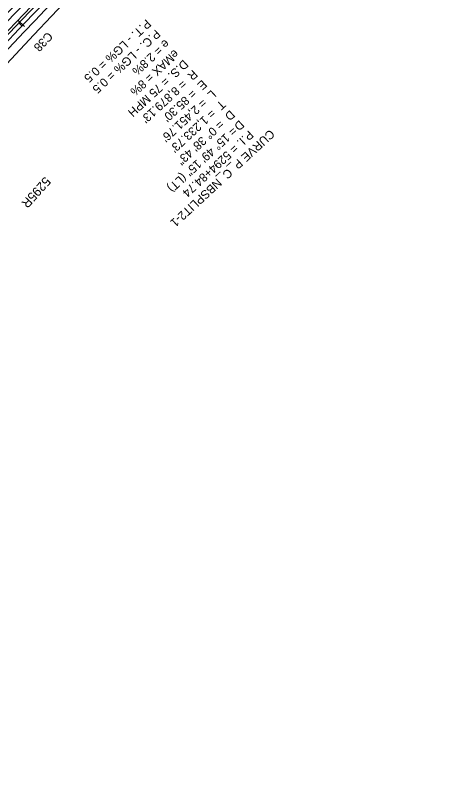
# Model space of a CAD drawing. Extents: x 2160877 to 2175861, y 601747 to 617724.
# Drawn here: x 2163357 to 2164133, y 604108 to 605468 of the extents above; entities that cross this region are included whole.
import ezdxf

# ---------------------------------------------------------------- set-up
doc = ezdxf.new("R2010")
doc.units = 0
for name, color, linetype in [('RD_HC_Cl', 7, 'Continuous'), ('RD_HC_CL_Rel', 7, 'Continuous'), ('RD_HC_Data_Rel', 7, 'Continuous'), ('RD_HC_Data_Tic', 7, 'Continuous'), ('RD_HC_Data_Tic_Rel', 7, 'Continuous'), ('RD_HC_TX_Rel_Sta50', 7, 'Continuous'), ('RD_PD_CstnLmt', 7, 'Continuous'), ('RD_PD_CstnLmt_TX', 7, 'Continuous'), ('RD_PD_Final_LnLine', 7, 'Continuous'), ('RD_PD_Final_TrvlWay', 7, 'Continuous')]:
    doc.layers.add(name, color=color, linetype=linetype)

msp = doc.modelspace()

# ---------------------------------------------------------------- linework, layer by layer
at = {"layer": 'RD_HC_Cl'}
for radius in [8641.9, 8545.9]:
    msp.add_arc((2169535, 599544.7), radius, 132.71947, 164.41949, dxfattribs=at)
at = {"layer": 'RD_HC_CL_Rel'}
for centre, radius, end in [((2169810, 599356.6), 8879.1, 145.62858), ((2169305.2, 599690.4), 8369.8, 147.62243)]:
    msp.add_arc(centre, radius, 129.80773, end, dxfattribs=at)
at = {"layer": 'RD_HC_Data_Tic'}
msp.add_line((2163362.5, 605455.2), (2163368.3, 605449.6), dxfattribs=at)
at = {"layer": 'RD_HC_Data_Tic_Rel'}
msp.add_line((2163361.2, 605460), (2163372.8, 605449), dxfattribs=at)
at = {"layer": 'RD_PD_CstnLmt'}
for p, q in [((2163457.1, 605506.3), (2163388.7, 605434)), ((2163388.7, 605434), (2163320.6, 605361.3))]:
    msp.add_line(p, q, dxfattribs=at)
at = {"layer": 'RD_PD_Final_LnLine'}
for centre, radius, end in [((2169810, 599356.6), 8891.1, 145.62858), ((2169810, 599356.6), 8867.1, 144.89859), ((2169305.2, 599690.4), 8381.8, 136.90521), ((2169305.2, 599690.4), 8357.8, 147.62243)]:
    msp.add_arc(centre, radius, 129.80773, end, dxfattribs=at)
at = {"layer": 'RD_PD_Final_TrvlWay'}
for centre, radius, start, end in [((2169810, 599356.6), 8901.1, 129.80773, 142.13894), ((2169305.2, 599690.4), 8391.8, 129.80773, 137.30123), ((2169305.2, 599690.4), 8347.8, 129.80773, 143.57306), ((2169810, 599356.6), 8857.1, 131.47407, 142.45996)]:
    msp.add_arc(centre, radius, start, end, dxfattribs=at)

# ---------------------------------------------------------------- texts
at = {"layer": 'RD_HC_Data_Rel'}
for s, p in [('P.T. - LG% = 0.5', (2163585.5, 605462.3)), ('P.C. - LG% = 0.5', (2163601.8, 605444.6)), ('e = 2.8%', (2163618.1, 605427)), ('eMAX = 8%', (2163634.4, 605409.4)), ('D.S. = 75 MPH', (2163650.7, 605391.7)), ("R  = 8,879.13'", (2163666.9, 605374.1)), ("E  = 85.30'", (2163683.2, 605356.5)), ("L  = 2,451.76'", (2163699.5, 605338.8)), ("T  = 1,233.73'", (2163715.8, 605321.2)), ('D  = 0%%d 38\' 43"', (2163732.1, 605303.6)), ('D ', (2163748.4, 605286)), ('   = 15%%d 49\' 15" (LT)', (2163748.4, 605286)), ('CURVE P_C_NBSPLIT2-1', (2163801.6, 605269.8)), ('P.I. = 5294+84.74', (2163764.6, 605268.3))]:
    msp.add_text(s, height=15, rotation=222.7195, dxfattribs=at).set_placement(p)
at = {"layer": 'RD_HC_TX_Rel_Sta50'}
msp.add_text('5295R', height=16, rotation=227.8673, dxfattribs=at).set_placement((2163408.2, 605187.4))
at = {"layer": 'RD_PD_CstnLmt_TX'}
msp.add_text('C38', height=15, rotation=226.5767, dxfattribs=at).set_placement((2163412.8, 605440.4))

doc.saveas('drawing.dxf')
